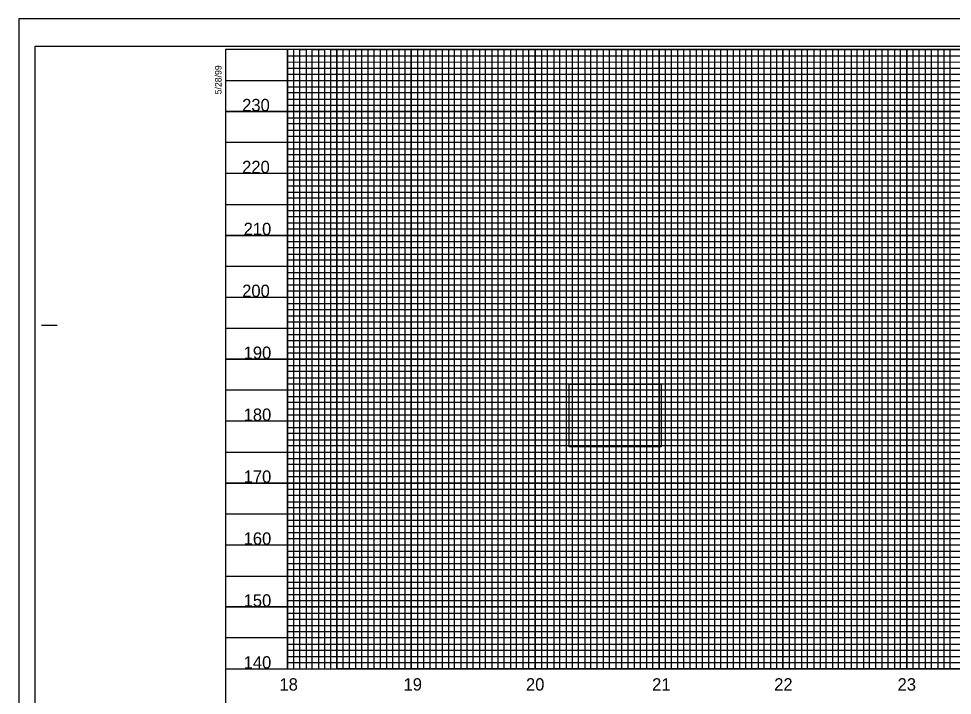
# Model space of a CAD drawing. Extents: x 1779926 to 1781610, y 620464 to 621564.
# Drawn here: x 1779926 to 1780680, y 621018 to 621564 of the extents above; entities that cross this region are included whole.
import ezdxf

# ---------------------------------------------------------------- set-up
doc = ezdxf.new("R2010")
doc.units = 0
for name, color, linetype in [('Exist Vertical Profile Horizontal Axis Label Major', 7, 'Continuous'), ('Exist Vertical Profile Vertical Axis Label', 7, 'Continuous'), ('Prop Grid Mask', 7, 'Continuous'), ('Scratch_Level_0', 7, 'Continuous'), ('Sheet Cutting Line CELL', 7, 'Continuous'), ('Sheet DOT Grid CELL', 7, 'Continuous'), ('Sheet Layout Profile Border Port 1', 7, 'Continuous'), ('Sheet Plot Border Inside CELL', 7, 'Continuous'), ('Sheet Plot Border Outside CELL', 7, 'Continuous'), ('Sheet Profile CELL', 7, 'Continuous'), ('Sheet Profile Grid Major CELL', 7, 'Continuous'), ('Sheet Profile Grid Middle CELL', 7, 'Continuous'), ('Sheet Profile Grid Minor CELL', 7, 'Continuous')]:
    doc.layers.add(name, color=color, linetype=linetype)

msp = doc.modelspace()

# ---------------------------------------------------------------- linework, layer by layer
at = {"layer": 'Prop Grid Mask'}
msp.add_lwpolyline([(1780370.35, 621269.13), (1780444.73, 621269.13), (1780444.73, 621218.62), (1780370.35, 621218.62)], close=True, dxfattribs=at)
at = {"layer": 'Scratch_Level_0'}
msp.add_lwpolyline([(1780192.96, 621039.19), (1780192.96, 621539.19), (1781392.96, 621539.19), (1781392.96, 621314.19), (1781542.96, 621314.19), (1781542.96, 621039.19)], close=True, dxfattribs=at)
at = {"layer": 'Sheet Cutting Line CELL'}
for p, q in [((1781609.96, 621564.19), (1779925.96, 621564.19)), ((1779925.96, 621564.19), (1779925.96, 620464.19))]:
    msp.add_line(p, q, dxfattribs=at)
at = {"layer": 'Sheet DOT Grid CELL'}
for p, q in [((1780142.96, 621039.19), (1780142.96, 621539.19)), ((1780192.96, 621039.19), (1780192.96, 621539.19)), ((1780242.96, 621039.19), (1780242.96, 621539.19)), ((1780292.96, 621039.19), (1780292.96, 621539.19)), ((1780342.96, 621039.19), (1780342.96, 621539.19)), ((1780392.96, 621039.19), (1780392.96, 621539.19)), ((1780442.96, 621039.19), (1780442.96, 621539.19)), ((1780492.96, 621039.19), (1780492.96, 621539.19)), ((1780542.96, 621039.19), (1780542.96, 621539.19)), ((1780592.96, 621039.19), (1780592.96, 621539.19)), ((1780642.96, 621039.19), (1780642.96, 621539.19)), ((1781392.91, 621489.19), (1780092.96, 621489.19)), ((1781392.91, 621439.19), (1780092.96, 621439.19)), ((1781392.96, 621389.19), (1780092.96, 621389.19)), ((1781392.91, 621339.19), (1780092.96, 621339.19)), ((1781592.96, 621289.19), (1780092.96, 621289.19)), ((1781592.96, 621239.19), (1780092.96, 621239.19)), ((1781592.96, 621189.19), (1780092.96, 621189.19)), ((1781592.96, 621139.19), (1780092.96, 621139.19)), ((1781592.96, 621089.19), (1780092.96, 621089.19))]:
    msp.add_line(p, q, dxfattribs=at)
at = {"layer": 'Sheet Layout Profile Border Port 1'}
msp.add_lwpolyline([(1781392.96, 621539.19), (1781392.9, 621314.19), (1781532.96, 621314.19), (1781532.96, 621039.19), (1780182.96, 621039.19), (1780182.96, 621539.19)], close=True, dxfattribs=at)
msp.add_lwpolyline([(1780142.96, 621378.14), (1780142.96, 621039.19), (1781542.96, 621039.19), (1781542.96, 621314.19)], dxfattribs=at)
at = {"layer": 'Sheet Plot Border Inside CELL'}
msp.add_lwpolyline([(1779938.96, 620486.64), (1781605.46, 620486.64), (1781605.46, 621541.74), (1779938.96, 621541.74)], close=True, dxfattribs=at)
at = {"layer": 'Sheet Plot Border Outside CELL'}
msp.add_lwpolyline([(1779925.96, 620464.19), (1781609.96, 620464.19), (1781609.96, 621564.19), (1779925.96, 621564.19)], close=True, dxfattribs=at)
at = {"layer": 'Sheet Profile CELL'}
for p, q in [((1779944.46, 621316.69), (1779956.96, 621316.69)), ((1780092.96, 621039.19), (1781592.96, 621039.19))]:
    msp.add_line(p, q, dxfattribs=at)
msp.add_lwpolyline([(1781592.96, 621539.19), (1780092.96, 621539.19), (1780092.96, 620489.19), (1781592.96, 620489.19)], close=True, dxfattribs=at)
at = {"layer": 'Sheet Profile Grid Major CELL'}
for points in [[(1780142.96, 621539.19), (1780142.96, 621039.19), (1780192.96, 621039.19), (1780192.96, 621539.19), (1780242.96, 621539.19), (1780242.96, 621039.19), (1780292.96, 621039.19), (1780292.96, 621539.19), (1780342.96, 621539.19), (1780342.96, 621039.19), (1780392.96, 621039.19), (1780392.96, 621539.19), (1780442.96, 621539.19), (1780442.96, 621039.19), (1780492.96, 621039.19), (1780492.96, 621539.19), (1780542.96, 621539.19), (1780542.96, 621039.19), (1780592.96, 621039.19), (1780592.96, 621539.19), (1780642.96, 621539.19), (1780642.96, 621039.19), (1780692.96, 621039.19)], [(1780092.96, 621489.19), (1781392.96, 621489.19)], [(1781392.96, 621439.19), (1780092.96, 621439.19), (1780092.96, 621389.19), (1781392.96, 621389.19)], [(1781392.91, 621339.19), (1780092.96, 621339.19), (1780092.96, 621289.19), (1781592.96, 621289.19)], [(1781592.96, 621239.19), (1780092.96, 621239.19), (1780092.96, 621189.19), (1781592.96, 621189.19)], [(1781592.96, 621139.19), (1780092.96, 621139.19), (1780092.96, 621139.19), (1780092.96, 621089.19), (1781592.96, 621089.19)]]:
    msp.add_lwpolyline(points, dxfattribs=at)
at = {"layer": 'Sheet Profile Grid Middle CELL'}
msp.add_line((1780092.96, 621514.19), (1781392.91, 621514.19), dxfattribs=at)
for points in [[(1780167.96, 621539.19), (1780167.96, 621039.19), (1780217.96, 621039.19), (1780217.96, 621539.19), (1780267.96, 621539.19), (1780267.96, 621039.19), (1780317.96, 621039.19), (1780317.96, 621539.19), (1780367.96, 621539.19), (1780367.96, 621039.19), (1780417.96, 621039.19), (1780417.96, 621539.19), (1780467.96, 621539.19), (1780467.96, 621039.19), (1780517.96, 621039.19), (1780517.96, 621539.19), (1780567.96, 621539.19), (1780567.96, 621039.19), (1780617.96, 621039.19), (1780617.96, 621539.19), (1780667.96, 621539.19), (1780667.96, 621039.19), (1780717.96, 621039.19)], [(1781392.96, 621464.19), (1780092.96, 621464.19), (1780092.96, 621414.19), (1781392.96, 621414.19)], [(1781392.91, 621364.19), (1780092.96, 621364.19), (1780092.96, 621314.19), (1781417.96, 621314.19)], [(1781592.96, 621264.19), (1780092.96, 621264.19), (1780092.96, 621214.19), (1781592.96, 621214.19)], [(1781592.96, 621164.19), (1780092.96, 621164.19), (1780092.96, 621114.19), (1781592.96, 621114.19)], [(1781592.96, 621064.19), (1780092.96, 621064.19)]]:
    msp.add_lwpolyline(points, dxfattribs=at)
at = {"layer": 'Sheet Profile Grid Minor CELL'}
for p, q in [((1780142.96, 621534.19), (1781392.96, 621534.19)), ((1780142.96, 621529.19), (1780142.96, 621529.19)), ((1781392.96, 621529.19), (1780142.96, 621528.84)), ((1780142.96, 621524.19), (1781392.96, 621524.19)), ((1781392.91, 621404.19), (1780142.96, 621404.19)), ((1781392.96, 621399.19), (1780142.96, 621399.19)), ((1781392.96, 621394.19), (1780142.96, 621394.19)), ((1780142.96, 621384.19), (1781392.96, 621384.19)), ((1781392.96, 621379.19), (1780142.96, 621379.19)), ((1780142.96, 621374.19), (1781392.96, 621374.19)), ((1781392.96, 621354.19), (1780142.96, 621354.19)), ((1780142.96, 621349.19), (1781392.96, 621349.19)), ((1781392.91, 621329.19), (1780142.96, 621329.19)), ((1780142.96, 621324.19), (1781392.91, 621324.19)), ((1781542.96, 621304.19), (1780142.96, 621304.19)), ((1780142.96, 621299.19), (1781542.96, 621299.19)), ((1781542.96, 621294.19), (1780142.96, 621294.19)), ((1780142.96, 621284.19), (1781542.96, 621284.19)), ((1781542.96, 621279.19), (1780142.96, 621279.19)), ((1780142.96, 621274.19), (1781542.96, 621274.19)), ((1781542.96, 621269.19), (1780142.96, 621269.19)), ((1780142.96, 621259.19), (1781542.96, 621259.19)), ((1781542.96, 621254.19), (1780142.96, 621254.19)), ((1780142.96, 621249.19), (1781542.96, 621249.19)), ((1781542.96, 621244.19), (1780142.96, 621244.19)), ((1780142.96, 621234.19), (1781542.96, 621234.19)), ((1781542.96, 621229.19), (1780142.96, 621229.19)), ((1780142.96, 621224.19), (1781542.96, 621224.19)), ((1781542.96, 621219.19), (1780142.96, 621219.19)), ((1780142.96, 621209.19), (1781542.96, 621209.19)), ((1781542.96, 621204.19), (1780142.96, 621204.19)), ((1780142.96, 621199.19), (1781542.96, 621199.19)), ((1781542.96, 621194.19), (1780142.96, 621194.19)), ((1780142.96, 621184.19), (1781542.96, 621184.19)), ((1781542.96, 621179.19), (1780142.96, 621179.19)), ((1780142.96, 621174.19), (1781542.96, 621174.19)), ((1781542.96, 621169.19), (1780142.96, 621169.19)), ((1780142.96, 621159.19), (1781542.96, 621159.19)), ((1781542.96, 621154.19), (1780142.96, 621154.19)), ((1781542.96, 621149.19), (1780142.96, 621149.19)), ((1781542.96, 621144.19), (1780142.96, 621144.19)), ((1780142.96, 621134.19), (1781542.96, 621134.19)), ((1781542.96, 621129.19), (1780142.96, 621129.19)), ((1780142.96, 621124.19), (1781542.96, 621124.19)), ((1781542.96, 621119.19), (1780142.96, 621119.19)), ((1780142.96, 621109.19), (1781542.96, 621109.19)), ((1781542.96, 621104.19), (1780142.96, 621104.19)), ((1780142.96, 621099.19), (1781542.96, 621099.19)), ((1781542.96, 621094.19), (1780142.96, 621094.19)), ((1780142.96, 621084.19), (1781542.96, 621084.19)), ((1781542.96, 621079.19), (1780142.96, 621079.19)), ((1780142.96, 621074.19), (1781542.96, 621074.19)), ((1781542.96, 621069.19), (1780142.96, 621069.19)), ((1780142.96, 621059.19), (1781542.96, 621059.19)), ((1781542.96, 621054.19), (1780142.96, 621054.19)), ((1780142.96, 621049.19), (1781542.96, 621049.19))]:
    msp.add_line(p, q, dxfattribs=at)
for points in [[(1780147.96, 621539.19), (1780147.96, 621039.19), (1780152.96, 621039.19), (1780152.96, 621539.19), (1780157.96, 621539.19), (1780157.96, 621039.19), (1780162.96, 621039.19), (1780162.96, 621539.19), (1780172.96, 621539.19), (1780172.96, 621039.19), (1780177.96, 621039.19), (1780177.96, 621539.19), (1780182.96, 621539.19), (1780182.96, 621039.19), (1780187.96, 621039.19), (1780197.96, 621039.19), (1780202.96, 621039.19), (1780202.96, 621539.19), (1780207.96, 621539.19), (1780207.96, 621039.19), (1780212.96, 621039.19), (1780212.96, 621539.19), (1780222.96, 621539.19), (1780222.96, 621039.19), (1780227.96, 621039.19), (1780227.96, 621539.19), (1780232.96, 621539.19), (1780232.96, 621039.19), (1780237.96, 621039.19), (1780237.96, 621539.19), (1780247.96, 621539.19), (1780247.96, 621039.19), (1780252.96, 621039.19), (1780252.96, 621539.19), (1780257.96, 621539.19), (1780257.96, 621039.19), (1780262.96, 621039.19), (1780262.96, 621539.19), (1780272.96, 621539.19), (1780272.96, 621039.19), (1780277.96, 621039.19), (1780277.96, 621539.19), (1780282.96, 621539.19), (1780282.96, 621039.19), (1780287.96, 621039.19), (1780287.96, 621539.19), (1780297.96, 621539.19), (1780297.96, 621039.19), (1780302.96, 621039.19), (1780302.96, 621539.19), (1780307.96, 621539.19), (1780307.96, 621039.19), (1780312.96, 621039.19), (1780312.96, 621539.19), (1780322.96, 621539.19), (1780322.96, 621039.19), (1780327.96, 621039.19), (1780327.96, 621539.19), (1780332.96, 621539.19), (1780332.96, 621039.19), (1780337.96, 621039.19), (1780337.96, 621539.19), (1780347.96, 621539.19), (1780347.96, 621039.19), (1780352.96, 621039.19), (1780352.96, 621539.19), (1780357.96, 621539.19), (1780357.96, 621039.19)], [(1780187.96, 621039.19), (1780187.96, 621539.19), (1780197.96, 621539.19), (1780197.96, 621039.19)], [(1780357.96, 621039.19), (1780362.96, 621039.19), (1780362.96, 621539.19), (1780372.96, 621539.19), (1780372.96, 621039.19), (1780377.96, 621039.19), (1780377.96, 621539.19), (1780382.96, 621539.19), (1780382.96, 621039.19), (1780387.96, 621039.19), (1780387.96, 621539.19), (1780397.96, 621539.19), (1780397.96, 621039.19), (1780402.96, 621039.19), (1780402.96, 621539.19), (1780407.96, 621539.19), (1780407.96, 621039.19), (1780412.96, 621039.19), (1780412.96, 621539.19), (1780422.96, 621539.19), (1780422.96, 621039.19), (1780427.96, 621039.19), (1780427.96, 621539.19), (1780432.96, 621539.19), (1780432.96, 621039.19), (1780437.96, 621039.19), (1780437.96, 621539.19), (1780447.96, 621539.19), (1780447.96, 621039.19), (1780452.96, 621039.19), (1780452.96, 621539.19), (1780457.96, 621539.19), (1780457.96, 621039.19), (1780462.96, 621039.19), (1780462.96, 621539.19), (1780472.96, 621539.19), (1780472.96, 621039.19), (1780477.96, 621039.19), (1780477.96, 621539.19), (1780482.96, 621539.19), (1780482.96, 621039.19), (1780487.96, 621039.19), (1780487.96, 621539.19), (1780497.96, 621539.19), (1780497.96, 621039.19), (1780502.96, 621039.19), (1780502.96, 621539.19), (1780507.96, 621539.19), (1780507.96, 621039.19), (1780512.96, 621039.19), (1780512.96, 621539.19), (1780522.96, 621539.19), (1780522.96, 621039.19), (1780527.96, 621039.19), (1780527.96, 621539.19), (1780532.96, 621539.19), (1780532.96, 621039.19), (1780537.96, 621039.19), (1780537.96, 621539.19), (1780547.96, 621539.19), (1780547.96, 621039.19), (1780552.96, 621039.19), (1780552.96, 621539.19), (1780557.96, 621539.19), (1780557.96, 621039.19), (1780562.96, 621039.19), (1780562.96, 621539.19), (1780572.96, 621539.19), (1780572.96, 621039.19), (1780577.96, 621039.19), (1780577.96, 621539.19), (1780582.96, 621539.19), (1780582.96, 621039.19), (1780587.96, 621039.19), (1780587.96, 621539.19), (1780597.96, 621539.19), (1780597.96, 621039.19), (1780602.96, 621039.19), (1780602.96, 621539.19), (1780607.96, 621539.19), (1780607.96, 621039.19), (1780612.96, 621039.19), (1780612.96, 621539.19), (1780622.96, 621539.19), (1780622.96, 621039.19), (1780627.96, 621039.19), (1780627.96, 621539.19), (1780632.96, 621539.19), (1780632.96, 621039.19), (1780637.96, 621039.19), (1780637.96, 621539.19), (1780647.96, 621539.19), (1780647.96, 621039.19), (1780652.96, 621039.19), (1780652.96, 621539.19), (1780657.96, 621539.19), (1780657.96, 621039.19), (1780662.96, 621039.19), (1780662.96, 621539.19), (1780672.96, 621539.19)], [(1780672.96, 621539.19), (1780672.96, 621039.19), (1780677.96, 621039.19), (1780677.96, 621539.19), (1780682.96, 621539.19)], [(1781392.96, 621519.19), (1780142.96, 621519.19), (1780142.96, 621509.19), (1781392.96, 621509.19)], [(1781392.91, 621504.19), (1780142.96, 621504.19), (1780142.96, 621499.19), (1781392.96, 621499.19)], [(1781392.96, 621494.19), (1780142.96, 621494.19), (1780142.96, 621484.19), (1781392.96, 621484.19)], [(1781392.96, 621479.19), (1780142.96, 621479.19), (1780142.96, 621474.19), (1781392.96, 621474.19)], [(1781392.96, 621469.19), (1780142.96, 621469.19), (1780142.96, 621459.19), (1781392.96, 621459.19)], [(1781392.96, 621454.19), (1780142.96, 621454.19), (1780142.96, 621449.19), (1781392.96, 621449.19)], [(1781392.96, 621444.19), (1780142.96, 621444.19), (1780142.96, 621434.19), (1781392.96, 621434.19)], [(1781392.96, 621429.09), (1780143.06, 621429.09), (1780143.06, 621424.19), (1781392.96, 621424.19)], [(1781392.96, 621419.19), (1780142.96, 621419.19), (1780142.96, 621409.19), (1781392.96, 621409.19)], [(1781392.91, 621369.19), (1780142.96, 621369.19), (1780142.96, 621359.19), (1781392.91, 621359.19)], [(1781392.91, 621344.19), (1780142.96, 621344.19), (1780142.96, 621334.19), (1781392.91, 621334.19)], [(1781392.91, 621319.19), (1780142.96, 621319.19), (1780142.96, 621309.19), (1781542.96, 621309.19)], [(1781542.96, 621044.19), (1780142.96, 621044.19)]]:
    msp.add_lwpolyline(points, dxfattribs=at)

# ---------------------------------------------------------------- texts
at = {"layer": 'Exist Vertical Profile Horizontal Axis Label Major'}
for s, p in [('18', (1780136.51, 621021.69)), ('19', (1780236.69, 621021.69)), ('20', (1780335.53, 621021.69)), ('21', (1780437.39, 621021.69)), ('22', (1780535.93, 621021.69)), ('23', (1780635.57, 621021.69))]:
    msp.add_text(s, height=10, dxfattribs=at).set_placement(p)
at = {"layer": 'Exist Vertical Profile Vertical Axis Label'}
for s, p in [('230', (1780106.39, 621489.44)), ('220', (1780106.39, 621439.44)), ('210', (1780107.59, 621389.44)), ('200', (1780106.39, 621339.44)), ('190', (1780107.59, 621289.44)), ('180', (1780107.59, 621239.44)), ('170', (1780107.59, 621189.44)), ('160', (1780107.59, 621139.44)), ('150', (1780107.59, 621089.44)), ('140', (1780107.59, 621039.44))]:
    msp.add_text(s, height=10, dxfattribs=at).set_placement(p)
at = {"layer": 'Sheet Profile CELL'}
msp.add_text('5/28/99', height=5.25, rotation=90, dxfattribs=at).set_placement((1780089.72, 621503.1))

doc.saveas('drawing.dxf')
